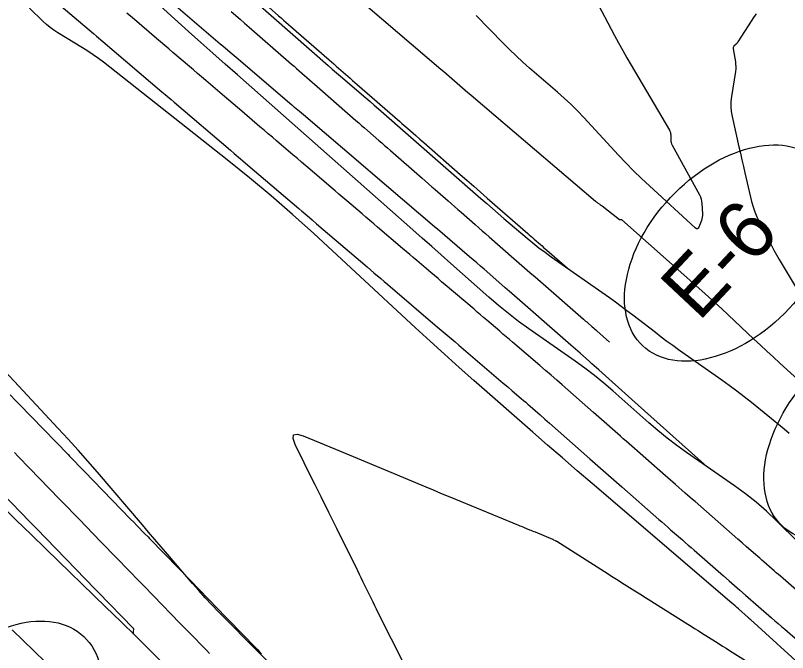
# Model space of a CAD drawing. Extents: x 1005228 to 1008882, y 1883389 to 1885754.
# Drawn here: x 1007083.3 to 1007166.4, y 1885333.3 to 1885401.9 of the extents above; entities that cross this region are included whole.
import ezdxf

# ---------------------------------------------------------------- set-up
doc = ezdxf.new("R2010")
doc.units = 0
for name, color, linetype in [('ATDIMS', 7, 'Continuous'), ('C-ANNO-NOTE', 7, 'Continuous'), ('R_Erosion', 7, 'Continuous'), ('S_BRIDGE', 7, 'Continuous'), ('TSOBSTACLE', 7, 'Continuous')]:
    doc.layers.add(name, color=color, linetype=linetype)

msp = doc.modelspace()

# ---------------------------------------------------------------- linework, layer by layer
at = {"layer": 'ATDIMS'}
msp.add_lwpolyline([(1007106.489, 1885402.353), (1007107.453, 1885401.511), (1007107.935, 1885401.09), (1007108.417, 1885400.669), (1007112.695, 1885396.931), (1007112.973, 1885396.689), (1007113.251, 1885396.446), (1007113.528, 1885396.204), (1007113.806, 1885395.961), (1007114.916, 1885394.991), (1007115.194, 1885394.749), (1007115.472, 1885394.506), (1007115.749, 1885394.264), (1007116.027, 1885394.021), (1007119.916, 1885390.623), (1007120.225, 1885390.353), (1007120.534, 1885390.083), (1007120.843, 1885389.813), (1007121.153, 1885389.543), (1007122.389, 1885388.463), (1007122.698, 1885388.193), (1007123.007, 1885387.923), (1007123.316, 1885387.653), (1007123.625, 1885387.383), (1007127.039, 1885384.401), (1007127.389, 1885384.095), (1007127.74, 1885383.789), (1007128.09, 1885383.483), (1007128.44, 1885383.177), (1007129.842, 1885381.953), (1007130.192, 1885381.647), (1007130.543, 1885381.341), (1007130.893, 1885381.034), (1007131.243, 1885380.728), (1007132.772, 1885379.392), (1007133.143, 1885379.068), (1007133.515, 1885378.743), (1007133.887, 1885378.418), (1007134.258, 1885378.094), (1007136.937, 1885375.754), (1007137.508, 1885375.255), (1007138.078, 1885374.757), (1007138.649, 1885374.259), (1007139.219, 1885373.761), (1007144.408, 1885369.229), (1007144.529, 1885369.124), (1007144.649, 1885369.018), (1007144.77, 1885368.913), (1007144.891, 1885368.807), (1007145.373, 1885368.386), (1007145.494, 1885368.28), (1007145.614, 1885368.174), (1007145.734, 1885368.068), (1007145.854, 1885367.961), (1007147.233, 1885366.728)], dxfattribs=at)
at = {"layer": 'C-ANNO-NOTE'}
for points in [[(1007103.167, 1885408.612), (1007116.924, 1885396.534), (1007117.372, 1885396.142), (1007117.821, 1885395.752), (1007118.271, 1885395.363), (1007118.723, 1885394.977), (1007120.534, 1885393.432), (1007120.986, 1885393.046), (1007121.436, 1885392.657), (1007121.886, 1885392.267), (1007122.334, 1885391.876), (1007133.379, 1885382.2), (1007133.996, 1885381.662), (1007134.615, 1885381.126), (1007135.236, 1885380.592), (1007135.858, 1885380.061), (1007138.354, 1885377.94), (1007138.983, 1885377.418), (1007139.625, 1885376.91), (1007140.277, 1885376.418), (1007140.942, 1885375.94), (1007147.227, 1885371.535), (1007147.858, 1885371.086), (1007148.484, 1885370.63), (1007149.105, 1885370.167), (1007149.72, 1885369.696), (1007152.17, 1885367.799), (1007152.785, 1885367.328), (1007153.405, 1885366.864), (1007154.031, 1885366.408), (1007154.662, 1885365.959), (1007159.303, 1885362.7), (1007160.119, 1885362.115), (1007160.924, 1885361.516), (1007161.718, 1885360.903), (1007162.502, 1885360.275), (1007166.016, 1885357.405), (1007166.584, 1885356.926)], [(1007169.974, 1885342.785), (1007165.212, 1885347.513), (1007164.141, 1885348.531), (1007163.029, 1885349.499), (1007161.875, 1885350.417), (1007160.68, 1885351.286), (1007155.508, 1885354.876), (1007154.459, 1885355.628), (1007153.432, 1885356.409), (1007152.429, 1885357.221), (1007151.449, 1885358.062), (1007147.577, 1885361.485), (1007146.598, 1885362.327), (1007145.596, 1885363.139), (1007144.572, 1885363.924), (1007143.524, 1885364.679), (1007138.524, 1885368.181), (1007137.414, 1885368.983), (1007136.328, 1885369.816), (1007135.267, 1885370.679), (1007134.23, 1885371.574), (1007130.133, 1885375.216), (1007129.108, 1885376.126), (1007128.083, 1885377.035), (1007127.056, 1885377.943), (1007126.029, 1885378.85), (1007107.152, 1885395.507), (1007105.833, 1885396.675), (1007104.518, 1885397.847), (1007103.207, 1885399.023), (1007101.9, 1885400.204), (1007094.331, 1885407.065)], [(1007169.047, 1885361.319), (1007165.569, 1885364.47), (1007164.864, 1885365.113), (1007164.162, 1885365.759), (1007163.464, 1885366.41), (1007162.769, 1885367.064), (1007159.998, 1885369.689), (1007159.302, 1885370.343), (1007158.601, 1885370.99), (1007157.894, 1885371.631), (1007157.181, 1885372.266), (1007148.539, 1885379.896), (1007148.523, 1885379.908), (1007148.505, 1885379.916), (1007148.485, 1885379.92), (1007148.465, 1885379.919), (1007148.38, 1885379.908), (1007148.359, 1885379.907), (1007148.34, 1885379.911), (1007148.321, 1885379.918), (1007148.304, 1885379.929), (1007146.445, 1885381.369), (1007146.385, 1885381.415), (1007146.325, 1885381.46), (1007146.264, 1885381.504), (1007146.203, 1885381.547), (1007145.957, 1885381.72), (1007145.896, 1885381.763), (1007145.836, 1885381.809), (1007145.778, 1885381.855), (1007145.72, 1885381.903), (1007132.567, 1885393.08), (1007132.274, 1885393.33), (1007131.982, 1885393.581), (1007131.691, 1885393.833), (1007131.4, 1885394.087), (1007130.242, 1885395.102), (1007129.952, 1885395.355), (1007129.661, 1885395.607), (1007129.369, 1885395.859), (1007129.076, 1885396.109), (1007117.989, 1885405.566)], [(1007186.684, 1885314.765), (1007162.389, 1885336.878), (1007162.379, 1885336.888), (1007162.368, 1885336.897), (1007162.358, 1885336.907), (1007162.348, 1885336.917), (1007162.243, 1885337.021), (1007162.236, 1885337.028), (1007162.229, 1885337.034), (1007162.222, 1885337.04), (1007162.214, 1885337.046), (1007162.183, 1885337.067), (1007162.175, 1885337.073), (1007162.167, 1885337.079), (1007162.16, 1885337.085), (1007162.153, 1885337.091), (1007161.097, 1885338.024), (1007160.918, 1885338.181), (1007160.739, 1885338.338), (1007160.559, 1885338.494), (1007160.379, 1885338.649), (1007145.355, 1885351.512), (1007143.752, 1885352.889), (1007142.155, 1885354.27), (1007140.561, 1885355.656), (1007138.972, 1885357.048), (1007132.624, 1885362.623), (1007131.041, 1885364.022), (1007129.468, 1885365.431), (1007127.903, 1885366.85), (1007126.347, 1885368.278), (1007115.366, 1885378.426), (1007113.1, 1885380.48), (1007110.794, 1885382.487), (1007108.451, 1885384.449), (1007106.068, 1885386.366), (1007092.732, 1885396.877), (1007092.187, 1885397.294), (1007091.63, 1885397.693), (1007091.06, 1885398.076), (1007090.48, 1885398.441), (1007087.821, 1885400.057), (1007087.398, 1885400.33), (1007086.992, 1885400.625), (1007086.603, 1885400.942), (1007086.23, 1885401.28), (1007084.763, 1885402.688)], [(1007163.004, 1885402.079), (1007162.735, 1885401.697), (1007162.478, 1885401.307), (1007161.055, 1885399.079), (1007161.009, 1885399.012), (1007160.96, 1885398.947), (1007160.907, 1885398.885), (1007160.851, 1885398.827), (1007160.618, 1885398.598), (1007160.569, 1885398.537), (1007160.537, 1885398.472), (1007160.524, 1885398.4), (1007160.529, 1885398.322), (1007160.773, 1885396.934), (1007160.807, 1885396.676), (1007160.82, 1885396.418), (1007160.811, 1885396.159), (1007160.781, 1885395.9), (1007160.35, 1885393.181), (1007160.291, 1885392.643), (1007160.283, 1885392.106), (1007160.326, 1885391.571), (1007160.421, 1885391.037), (1007161.16, 1885387.781), (1007161.32, 1885387.077), (1007161.482, 1885386.373), (1007161.644, 1885385.67), (1007161.808, 1885384.967), (1007162.528, 1885381.876), (1007162.676, 1885381.319), (1007162.858, 1885380.774), (1007163.073, 1885380.241), (1007163.321, 1885379.721), (1007164.38, 1885377.664), (1007164.649, 1885377.152), (1007164.926, 1885376.645), (1007165.212, 1885376.142), (1007165.505, 1885375.644), (1007167.448, 1885372.405)], [(1007123.023, 1885319.661), (1007105.132, 1885337.718), (1007104.409, 1885338.462), (1007103.699, 1885339.218), (1007103.003, 1885339.987), (1007102.321, 1885340.769), (1007099.619, 1885343.92), (1007098.944, 1885344.709), (1007098.269, 1885345.497), (1007097.594, 1885346.285), (1007096.919, 1885347.073), (1007092.082, 1885352.725), (1007091.045, 1885353.925), (1007089.994, 1885355.112), (1007088.931, 1885356.288), (1007087.855, 1885357.453), (1007080.725, 1885365.089)], [(1007099.373, 1885331.922), (1007097.791, 1885333.51), (1007096.201, 1885335.09), (1007094.603, 1885336.661), (1007092.996, 1885338.224), (1007086.552, 1885344.458), (1007084.944, 1885346.019), (1007083.34, 1885347.585), (1007081.742, 1885349.157)], [(1007092.358, 1885326.563), (1007082.886, 1885335.748)]]:
    msp.add_lwpolyline(points, dxfattribs=at)
at = {"layer": 'R_Erosion'}
for centre, major_axis in [((1007160.176, 1885376.333), (9.368, 9.993)), ((1007175.155, 1885356.977), (9.316, 10.041)), ((1007081.236, 1885325.059), (9.368, 9.993))]:
    msp.add_ellipse(centre, major_axis=major_axis, ratio=0.638788, dxfattribs=at)
at = {"layer": 'S_BRIDGE'}
msp.add_lwpolyline([(1007145.627, 1885403.802), (1007147.77, 1885399.767), (1007148.205, 1885398.956), (1007148.65, 1885398.151), (1007149.103, 1885397.351), (1007149.564, 1885396.555), (1007153.666, 1885389.568), (1007153.728, 1885389.445), (1007153.774, 1885389.318), (1007153.802, 1885389.185), (1007153.814, 1885389.049), (1007153.829, 1885388.491), (1007153.841, 1885388.354), (1007153.868, 1885388.221), (1007153.911, 1885388.092), (1007153.97, 1885387.968), (1007156.904, 1885382.597), (1007157.01, 1885382.376), (1007157.089, 1885382.149), (1007157.141, 1885381.913), (1007157.168, 1885381.67), (1007157.228, 1885380.566), (1007157.229, 1885380.38), (1007157.211, 1885380.197), (1007157.174, 1885380.016), (1007157.119, 1885379.839), (1007156.859, 1885379.135), (1007156.785, 1885378.997), (1007156.692, 1885378.934), (1007156.582, 1885378.948), (1007156.453, 1885379.037), (1007151.521, 1885383.565), (1007150.661, 1885384.37), (1007149.819, 1885385.193), (1007148.993, 1885386.033), (1007148.185, 1885386.89), (1007144.441, 1885390.943), (1007143.762, 1885391.656), (1007143.064, 1885392.35), (1007142.346, 1885393.023), (1007141.609, 1885393.676), (1007138.621, 1885396.248), (1007137.882, 1885396.899), (1007137.157, 1885397.567), (1007136.448, 1885398.25), (1007135.755, 1885398.95), (1007132.866, 1885401.93)], dxfattribs=at)
at = {"layer": 'TSOBSTACLE'}
for points in [[(1007084.957, 1885405.698), (1007091.65, 1885399.988), (1007091.994, 1885399.695), (1007092.68, 1885399.109), (1007099.029, 1885393.692), (1007099.358, 1885393.412), (1007100.015, 1885392.851), (1007100.344, 1885392.57), (1007106.398, 1885387.404), (1007106.801, 1885387.061), (1007107.472, 1885386.488), (1007107.74, 1885386.26), (1007108.009, 1885386.031), (1007113.76, 1885381.124), (1007114.079, 1885380.852), (1007114.399, 1885380.579), (1007115.197, 1885379.898), (1007115.676, 1885379.49), (1007121.111, 1885374.852), (1007121.483, 1885374.534), (1007121.855, 1885374.217), (1007122.6, 1885373.582), (1007122.972, 1885373.264), (1007123.344, 1885372.947), (1007128.453, 1885368.587), (1007128.667, 1885368.405), (1007128.88, 1885368.223), (1007129.094, 1885368.041), (1007129.307, 1885367.859), (1007130.161, 1885367.13), (1007130.588, 1885366.766), (1007131.015, 1885366.402), (1007135.784, 1885362.333), (1007136.268, 1885361.92), (1007136.752, 1885361.507), (1007137.719, 1885360.682), (1007137.961, 1885360.475), (1007138.202, 1885360.267), (1007138.441, 1885360.058), (1007138.68, 1885359.848), (1007139.74, 1885358.915), (1007140.252, 1885358.464), (1007140.765, 1885358.013), (1007145.114, 1885354.181), (1007145.4, 1885353.93), (1007145.685, 1885353.679), (1007145.97, 1885353.428), (1007146.255, 1885353.178), (1007147.397, 1885352.176), (1007147.683, 1885351.925), (1007147.968, 1885351.675), (1007148.254, 1885351.424), (1007148.539, 1885351.174), (1007152.548, 1885347.654), (1007152.863, 1885347.378), (1007153.177, 1885347.103), (1007153.492, 1885346.827), (1007153.807, 1885346.551), (1007155.066, 1885345.45), (1007155.381, 1885345.174), (1007155.696, 1885344.899), (1007156.011, 1885344.623), (1007156.326, 1885344.348), (1007159.507, 1885341.565), (1007160.093, 1885341.052), (1007160.681, 1885340.539), (1007161.268, 1885340.027), (1007161.856, 1885339.514), (1007164.679, 1885337.054), (1007165.03, 1885336.747), (1007165.382, 1885336.441), (1007165.734, 1885336.135), (1007166.085, 1885335.828), (1007167.492, 1885334.602)], [(1007157.749, 1885353.32), (1007152.34, 1885358.14), (1007151.661, 1885358.745), (1007150.982, 1885359.35), (1007150.304, 1885359.956), (1007149.626, 1885360.562), (1007146.058, 1885363.753), (1007145.808, 1885363.977), (1007145.559, 1885364.2), (1007145.309, 1885364.423), (1007145.059, 1885364.646), (1007144.061, 1885365.539), (1007143.811, 1885365.762), (1007143.56, 1885365.984), (1007143.309, 1885366.205), (1007143.057, 1885366.426), (1007136.403, 1885372.239), (1007136.252, 1885372.371), (1007135.989, 1885372.601), (1007135.951, 1885372.634), (1007133.708, 1885374.594), (1007133.321, 1885374.931), (1007132.933, 1885375.266), (1007132.544, 1885375.601), (1007132.154, 1885375.935), (1007128.69, 1885378.89), (1007128.394, 1885379.143), (1007121.479, 1885385.042), (1007121.218, 1885385.265), (1007120.697, 1885385.709), (1007114.255, 1885391.206), (1007114.046, 1885391.384), (1007113.838, 1885391.562), (1007113.316, 1885392.007), (1007113.108, 1885392.185), (1007113.004, 1885392.274), (1007107.015, 1885397.383), (1007106.59, 1885397.747), (1007105.88, 1885398.352), (1007105.596, 1885398.594), (1007105.312, 1885398.836), (1007099.763, 1885403.57)], [(1007170.52, 1885337.267), (1007165.627, 1885341.53), (1007165.405, 1885341.725), (1007165.182, 1885341.919), (1007164.959, 1885342.113), (1007164.737, 1885342.307), (1007163.846, 1885343.083), (1007163.623, 1885343.277), (1007163.401, 1885343.471), (1007163.178, 1885343.666), (1007162.956, 1885343.86), (1007161.984, 1885344.71), (1007161.512, 1885345.123), (1007161.04, 1885345.536), (1007156.432, 1885349.567), (1007156.167, 1885349.798), (1007155.902, 1885350.031), (1007155.638, 1885350.263), (1007155.373, 1885350.495), (1007154.314, 1885351.424), (1007154.049, 1885351.657), (1007153.785, 1885351.889), (1007153.52, 1885352.121), (1007153.255, 1885352.354), (1007149.002, 1885356.086), (1007148.709, 1885356.344), (1007148.415, 1885356.602), (1007148.122, 1885356.86), (1007147.828, 1885357.118), (1007146.656, 1885358.151), (1007146.362, 1885358.41), (1007146.069, 1885358.668), (1007145.776, 1885358.926), (1007145.483, 1885359.184), (1007142.134, 1885362.135), (1007141.535, 1885362.66), (1007140.935, 1885363.182), (1007140.332, 1885363.703), (1007139.728, 1885364.221), (1007136.786, 1885366.73), (1007136.44, 1885367.026), (1007136.094, 1885367.321), (1007135.748, 1885367.616), (1007135.401, 1885367.912), (1007134.016, 1885369.094), (1007133.67, 1885369.389), (1007133.324, 1885369.685), (1007132.977, 1885369.98), (1007132.631, 1885370.276), (1007129.524, 1885372.927), (1007129.142, 1885373.252), (1007128.76, 1885373.578), (1007128.379, 1885373.903), (1007127.997, 1885374.229), (1007126.471, 1885375.531), (1007126.089, 1885375.857), (1007125.707, 1885376.183), (1007125.326, 1885376.508), (1007124.944, 1885376.834), (1007122.247, 1885379.135), (1007121.831, 1885379.489), (1007121.416, 1885379.844), (1007121, 1885380.198), (1007120.585, 1885380.553), (1007118.923, 1885381.971), (1007118.507, 1885382.326), (1007118.092, 1885382.68), (1007117.676, 1885383.035), (1007117.261, 1885383.389), (1007114.959, 1885385.353), (1007114.511, 1885385.735), (1007114.063, 1885386.118), (1007113.614, 1885386.5), (1007113.166, 1885386.883), (1007111.373, 1885388.413), (1007110.924, 1885388.795), (1007110.476, 1885389.178), (1007110.028, 1885389.56), (1007109.58, 1885389.943), (1007107.643, 1885391.595), (1007107.171, 1885391.998), (1007106.699, 1885392.4), (1007106.227, 1885392.803), (1007105.755, 1885393.206), (1007103.744, 1885394.922), (1007103.302, 1885395.299), (1007102.86, 1885395.676), (1007102.419, 1885396.052), (1007101.977, 1885396.429), (1007100.211, 1885397.936), (1007099.769, 1885398.313), (1007099.327, 1885398.69), (1007098.886, 1885399.067), (1007098.444, 1885399.443), (1007096.069, 1885401.47), (1007095.244, 1885402.174)], [(1007110.52, 1885402.814), (1007111.584, 1885401.884), (1007111.85, 1885401.652), (1007112.117, 1885401.419), (1007112.383, 1885401.187), (1007112.649, 1885400.954), (1007117.018, 1885397.139), (1007117.271, 1885396.917), (1007117.524, 1885396.696), (1007117.777, 1885396.475), (1007118.03, 1885396.254), (1007119.043, 1885395.369), (1007119.297, 1885395.148), (1007119.55, 1885394.927), (1007119.803, 1885394.705), (1007120.056, 1885394.484), (1007124.629, 1885390.489), (1007124.844, 1885390.301), (1007125.059, 1885390.113), (1007125.274, 1885389.925), (1007125.49, 1885389.737), (1007126.351, 1885388.984), (1007126.781, 1885388.608), (1007127.212, 1885388.232), (1007131.142, 1885384.8), (1007131.868, 1885384.165), (1007132.595, 1885383.53), (1007133.322, 1885382.895), (1007134.048, 1885382.26), (1007138.418, 1885378.442), (1007138.589, 1885378.292), (1007138.76, 1885378.143), (1007138.931, 1885377.993), (1007139.102, 1885377.843), (1007139.787, 1885377.245), (1007139.959, 1885377.096), (1007140.13, 1885376.946), (1007140.301, 1885376.796), (1007140.472, 1885376.647), (1007142.666, 1885374.731)], [(1007082.673, 1885361.063), (1007083.287, 1885360.431), (1007083.656, 1885360.052), (1007088.923, 1885354.629), (1007089.069, 1885354.479), (1007089.215, 1885354.328), (1007089.361, 1885354.178), (1007089.507, 1885354.027), (1007090.239, 1885353.275), (1007090.677, 1885352.823), (1007095.656, 1885347.698), (1007095.997, 1885347.347), (1007096.338, 1885346.996), (1007097.19, 1885346.119), (1007097.531, 1885345.768), (1007097.701, 1885345.593), (1007102.381, 1885340.776), (1007102.772, 1885340.373), (1007103.163, 1885339.971), (1007103.945, 1885339.166), (1007104.336, 1885338.763), (1007104.727, 1885338.361), (1007109.096, 1885333.863), (1007109.318, 1885333.635), (1007109.539, 1885333.407), (1007109.761, 1885333.179)], [(1007125.168, 1885331.93), (1007122.326, 1885337.614), (1007122.139, 1885337.988), (1007121.953, 1885338.361), (1007121.768, 1885338.735), (1007121.583, 1885339.11), (1007120.843, 1885340.607), (1007120.658, 1885340.981), (1007120.473, 1885341.355), (1007120.289, 1885341.73), (1007120.104, 1885342.104), (1007117.843, 1885346.69), (1007117.633, 1885347.114), (1007117.424, 1885347.539), (1007117.214, 1885347.964), (1007117.005, 1885348.388), (1007116.166, 1885350.087), (1007115.957, 1885350.511), (1007115.748, 1885350.936), (1007115.538, 1885351.361), (1007115.329, 1885351.785), (1007113.385, 1885355.727), (1007113.144, 1885356.383), (1007113.206, 1885356.754), (1007113.572, 1885356.841), (1007114.243, 1885356.642), (1007118.315, 1885354.952), (1007118.746, 1885354.773), (1007119.177, 1885354.594), (1007119.608, 1885354.415), (1007120.038, 1885354.235), (1007121.761, 1885353.517), (1007122.192, 1885353.338), (1007122.623, 1885353.158), (1007123.054, 1885352.979), (1007123.485, 1885352.8), (1007127.434, 1885351.158), (1007128.236, 1885350.826), (1007129.038, 1885350.493), (1007129.841, 1885350.162), (1007130.644, 1885349.831), (1007137.432, 1885347.036), (1007137.579, 1885346.975), (1007137.727, 1885346.914), (1007137.875, 1885346.853), (1007138.023, 1885346.792), (1007138.613, 1885346.548), (1007138.761, 1885346.487), (1007138.909, 1885346.426), (1007139.056, 1885346.364), (1007139.204, 1885346.303), (1007141.068, 1885345.529), (1007141.103, 1885345.513), (1007141.138, 1885345.498), (1007141.173, 1885345.481), (1007141.207, 1885345.463), (1007141.388, 1885345.369), (1007141.4, 1885345.363), (1007141.413, 1885345.357), (1007141.425, 1885345.352), (1007141.438, 1885345.346), (1007141.489, 1885345.326), (1007141.502, 1885345.321), (1007141.514, 1885345.315), (1007141.526, 1885345.308), (1007141.538, 1885345.301), (1007147.091, 1885341.783), (1007147.448, 1885341.557), (1007147.805, 1885341.331), (1007148.162, 1885341.105), (1007148.52, 1885340.879), (1007149.95, 1885339.977), (1007150.307, 1885339.751), (1007150.665, 1885339.526), (1007151.022, 1885339.3), (1007151.38, 1885339.074), (1007155.639, 1885336.386), (1007156.014, 1885336.15), (1007156.389, 1885335.913), (1007156.764, 1885335.677), (1007157.14, 1885335.441), (1007158.641, 1885334.497), (1007159.016, 1885334.261), (1007159.392, 1885334.025), (1007159.767, 1885333.789), (1007160.142, 1885333.553), (1007163.979, 1885331.142)], [(1007104.138, 1885333.233), (1007103.821, 1885333.559), (1007103.504, 1885333.886), (1007102.235, 1885335.192), (1007101.918, 1885335.518), (1007101.6, 1885335.845), (1007101.283, 1885336.172), (1007100.966, 1885336.498), (1007098.12, 1885339.428), (1007097.771, 1885339.788), (1007097.421, 1885340.147), (1007097.072, 1885340.507), (1007096.722, 1885340.867), (1007095.324, 1885342.306), (1007094.975, 1885342.666), (1007094.625, 1885343.025), (1007094.276, 1885343.385), (1007093.926, 1885343.745), (1007091.456, 1885346.288), (1007091.075, 1885346.68), (1007090.694, 1885347.072), (1007090.314, 1885347.463), (1007089.933, 1885347.855), (1007088.411, 1885349.422), (1007088.03, 1885349.814), (1007087.649, 1885350.206), (1007087.269, 1885350.598), (1007086.888, 1885350.989), (1007084.78, 1885353.16), (1007084.369, 1885353.582), (1007083.958, 1885354.005), (1007083.548, 1885354.428), (1007083.137, 1885354.85)], [(1007095.947, 1885335.296), (1007095.964, 1885335.543), (1007095.967, 1885335.576), (1007095.97, 1885335.609), (1007095.974, 1885335.642), (1007095.978, 1885335.675), (1007095.995, 1885335.807), (1007095.996, 1885335.839), (1007095.989, 1885335.868), (1007095.977, 1885335.895), (1007095.957, 1885335.92), (1007092.115, 1885339.875), (1007091.845, 1885340.154), (1007085.511, 1885346.673), (1007085.272, 1885346.919), (1007084.794, 1885347.411), (1007078.893, 1885353.485)]]:
    msp.add_lwpolyline(points, dxfattribs=at)

# ---------------------------------------------------------------- texts
at = {"layer": 'R_Erosion'}
msp.add_text('E-6', height=6.2498, rotation=46.84988, dxfattribs=at).set_placement((1007156.814, 1885368.852))

doc.saveas('drawing.dxf')
